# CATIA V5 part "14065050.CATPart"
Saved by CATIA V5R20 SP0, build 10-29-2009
Part number: 14065050
Definition: NONE
Nomenclature: 14065050
Source: Unknown
Description: 14065050
Bounding box of the stored display mesh (mm): x -25 to 100, y -46.5 to 36.6, z -36.6 to 36.6
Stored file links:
  C:\Users\Utente\Desktop\IO LAVORO\3D X SITO CF\X SITO\PLASTICA\RF2\14065050.CATPart
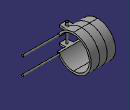
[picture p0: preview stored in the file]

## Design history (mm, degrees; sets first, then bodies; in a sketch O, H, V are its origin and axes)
Body1 "14065050" (main body)
  Solid1: solid without history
